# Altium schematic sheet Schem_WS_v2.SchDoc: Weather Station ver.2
size A3; DrawnBy: HienPhu; Engineer: HienPhu; Organization: QTech VietNam; Address1: ..........................; Address2: Đà Nẵng; Address3: Việt Nam; Address4: 09/2019; DocumentNumber: 1; Revision: 2.0; SheetNumber: 1; SheetTotal: 2
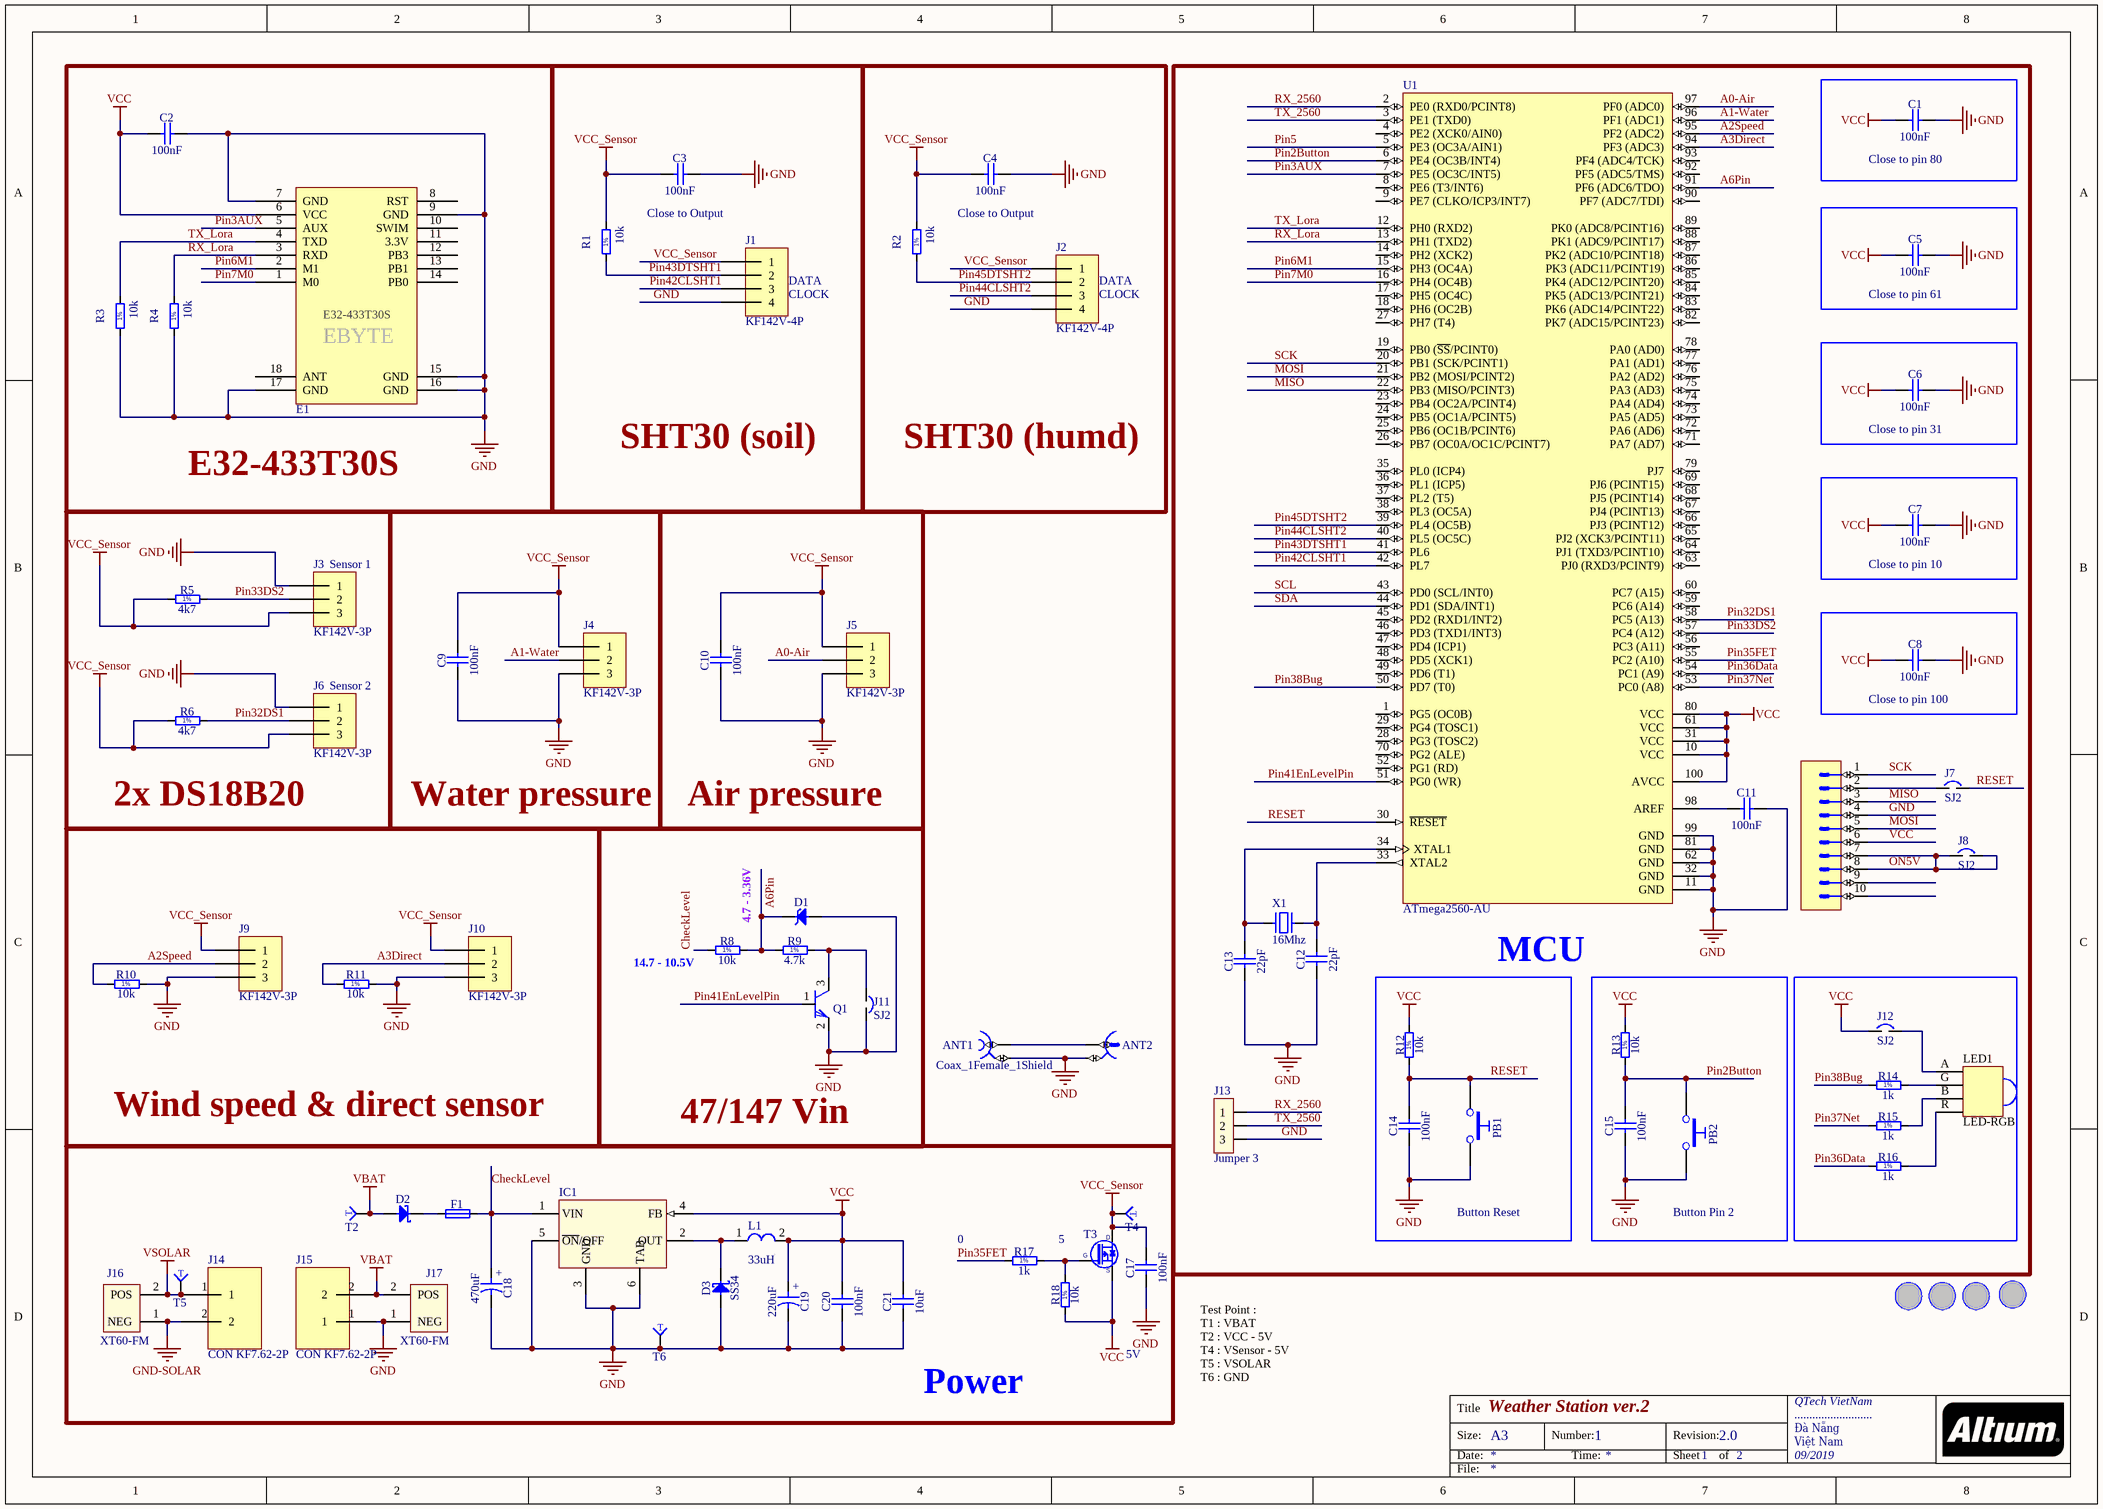
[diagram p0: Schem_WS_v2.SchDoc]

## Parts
ANT1  Coax_1Female_1Shield  [HUBER-SUHNER_85 SMA-50-0-101/111 NE]
ANT2  U.FL  [HIROSE_U.FL-R-SMT-1(10)]  (value not drawn)
C1  100nF  [CAPC1608X87N]
C2  100nF  [CAPC1608X87N]
C3  100nF  [CAPC1608X87N]
C4  100nF  [CAPC1608X87N]
C5  100nF  [CAPC1608X87N]
C6  100nF  [CAPC1608X87N]
C7  100nF  [CAPC1608X87N]
C8  100nF  [CAPC1608X87N]
C9  100nF  [CAPC1608X87N]
C10  100nF  [CAPC1608X87N]
C11  100nF  [CAPC1608X87N]
C12  22pF  [CAPC1608X87N]
C13  22pF  [CAPC1608X87N]
C14  100nF  [CAPC1608X87N]
C15  100nF  [CAPC1608X87N]
C17  100nF  [CAPC1608X87N]
C18  470uF  [CAPAE1030X1020N]
C19  220uF  [CAPMP6032X280N]
C20  100nF  [CAPC1608X87N]
C21  10uF  [CAPC2012X135N]
D1  BZV55-B5V1  [DIOMELF3515N]  (value not drawn)
D2  SS16  [DIOM5127X229N]  (value not drawn)
D3  SS34  [DIOM5127X229N]
E1  E32-T30S  [E32-433T30S]  (value not drawn)
F1  140mA-60V  [FUSRC4632X90N]  (value not drawn)
HOLE1  HOLE  [HOLE M3]  (value not drawn)
HOLE2  HOLE  [HOLE M3]  (value not drawn)
HOLE3  HOLE  [HOLE M3]  (value not drawn)
HOLE4  HOLE  [HOLE M3]  (value not drawn)
IC1  LM2596  [TO263-5]  (value not drawn)
J1  KF142V-4P  [CON KF142V-4P-5.08]
J2  KF142V-4P  [CON KF142V-4P-5.08]
J3  KF142V-3P  [CON KF142V-3P-5.08]
J4  KF142V-3P  [CON KF142V-3P-5.08]
J5  KF142V-3P  [CON KF142V-3P-5.08]
J6  KF142V-3P  [CON KF142V-3P-5.08]
J7  SJ2  [SJ2]
J8  SJ2  [SJ2]
J9  KF142V-3P  [CON KF142V-3P-5.08]
J10  KF142V-3P  [CON KF142V-3P-5.08]
J11  SJ2  [SJ2]
J12  SJ2  [SJ2]
J13  Jumper 3  [JP3]
J14  CON KF7.62-2P  [CON KF7.62-2P]
J15  CON KF7.62-2P  [CON KF7.62-2P]
J16  XT60-FM  [XT60-FM]
J17  XT60-FM  [XT60-FM]
JTAG1  Header 10  [3M_N2510-6002RB]  (value not drawn)
L1  33uH  [L_SMD]
LED1  LED-RGB  [LED-5MMRGBCA]
PB1  Push Button  [PB_TYCO_FSMSM]  (value not drawn)
PB2  Push Button  [PB_TYCO_FSMSM]  (value not drawn)
Q1  C1815  [SOT23]  (value not drawn)
R1  10k  [RESC1608X55N]
R2  10k  [RESC1608X55N]
R3  10k  [RESC1608X55N]
R4  10k  [RESC1608X55N]
R5  4k7  [RESC1608X55N]
R6  4k7  [RESC1608X55N]
R8  10k  [RESC1608X55N]
R9  4.7k  [RESC1608X55N]
R10  10k  [RESC1608X55N]
R11  10k  [RESC1608X55N]
R12  10k  [RESC1608X55N]
R13  10k  [RESC1608X55N]
R14  1k  [RESC1608X55N]
R15  1k  [RESC1608X55N]
R16  1k  [RESC1608X55N]
R17  1k  [RESC1608X55N]
R18  10k  [RESC1608X55N]
T2  Test Point  [TP1x1r]  (value not drawn)
T3  BSH203  [SOT95P230X110-3N]  (value not drawn)
T4  Test Point  [TP1x1r]  (value not drawn)
T5  Test Point  [TP1x1r]  (value not drawn)
T6  Test Point  [TP1x1r]  (value not drawn)
U1  ATmega2560-AU  [TQFP100L]
X1  16Mhz  [XT2]

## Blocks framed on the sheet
E32-433T30S: C2 E1 R3 R4
SHT30 (soil): C3 J1 R1
SHT30 (humd): C4 J2 R2
Button Reset: C11-C13 J7 J8 J12 J13 JTAG1 LED1 R14-R16 U1 X1
Close to pin 80: C1
Close to pin 61: C5
Close to pin 31: C6
Close to pin 10: C7
2x DS18B20: J3 J6 R5 R6
Water pressure: C9 J4
Air pressure: C10 J5
Close to pin 100: C8
Wind speed & direct sensor: J9 J10 R10 R11
47/147 Vin: D1 J11 Q1 R8 R9
MCU: C14 PB1 R12
Button Pin 2: C15 PB2 R13
Power: C17-C21 D2 D3 F1 IC1 J14-J17 L1 R17 R18 T2-T6

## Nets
GND: ANT1.2 ANT2.2 C1.2 C2.2 C3.2 C4.2 C5.2 C6.2 C7.2 C8.2 C9.1 C10.1 C11.2 C12.1 C13.1 C14.1 C15.1 C17.1 C18.2 C19.2 C20.1 C21.1 D1.2(A) D3.2(A) E1.7(GND) E1.9(GND) E1.15(GND) E1.16(GND) E1.17(GND) IC1.3(GND) IC1.5(~{ON}/OFF) IC1.6(TAB) J1.4 J2.4 J3.1 J4.3 J5.3 J6.1 J9.3 J10.3 J11.2 J13.3 J15.1 J17.1(NEG) JTAG1.4 PB1.2 PB2.2 Q1.2(E) R3.1 R4.1 R10.2 R11.2 T6.1 U1.11(GND) U1.32(GND) U1.62(GND) U1.81(GND) U1.99(GND)
GND-SOLAR: J14.2 J16.1(NEG)
VBAT: D2.2(A) J15.2 J17.2(POS) T2.1
VCC: C1.1 C2.1 C5.1 C6.1 C7.1 C8.1 C19.1 C20.2 C21.2 E1.6(VCC) IC1.4(FB) J12.1 JTAG1.6 L1.2 R12.2 R13.2 R18.1 T3.2(S) U1.10(VCC) U1.31(VCC) U1.61(VCC) U1.80(VCC) U1.100(AVCC)
VCC_Sensor: C3.1 C4.1 C9.2 C10.2 C17.2 J1.1 J2.1 J3.3 J4.1 J5.1 J6.3 J9.1 J10.1 R1.2 R2.2 R5.1 R6.1 T3.3(D) T4.1
VSOLAR: J14.1 J16.2(POS) T5.1
A0-Air: J5.2 U1.97(PF0_(ADC0))
A1-Water: J4.2 U1.96(PF1_(ADC1))
A2Speed: J9.2 R10.1 U1.95(PF2_(ADC2))
A3Direct: J10.2 R11.1 U1.94(PF3_(ADC3))
A6Pin: D1.1(C) R8.2 R9.1 U1.91(PF6_(ADC6/TDO))
CheckLevel: C18.1 F1.2 IC1.1(VIN) R8.1
MISO: JTAG1.3 U1.22(PB3_(MISO/PCINT3))
MOSI: JTAG1.5 U1.21(PB2_(MOSI/PCINT2))
ON5V: J8.1 J8.2 JTAG1.7 JTAG1.8
Pin2Button: C15.2 PB2.1 R13.1 U1.6(PE4_(OC3B/INT4))
Pin3AUX: E1.5(AUX) U1.7(PE5_(OC3C/INT5))
Pin5: U1.5(PE3_(OC3A/AIN1))
Pin6M1: E1.2(M1) U1.15(PH3_(OC4A))
Pin7M0: E1.1(M0) U1.16(PH4_(OC4B))
Pin32DS1: J6.2 R6.2 U1.58(PC5_(A13))
Pin33DS2: J3.2 R5.2 U1.57(PC4_(A12))
Pin35FET: R17.1 U1.55(PC2_(A10))
Pin36Data: R16.1 U1.54(PC1_(A9))
Pin37Net: R15.1 U1.53(PC0_(A8))
Pin38Bug: R14.1 U1.50(PD7_(T0))
Pin41EnLevelPin: Q1.1(B) U1.51(PG0_(WR))
Pin42CLSHT1: J1.3 U1.42(PL7)
Pin43DTSHT1: J1.2 R1.1 U1.41(PL6)
Pin44CLSHT2: J2.3 U1.40(PL5_(OC5C))
Pin45DTSHT2: J2.2 R2.1 U1.39(PL4_(OC5B))
RESET: C14.2 J7.2 PB1.1 R12.1 U1.30(~{RESET})
RX_2560: J13.1 U1.2(PE0_(RXD0/PCINT8))
RX_Lora: E1.3(RXD) R4.2 U1.13(PH1_(TXD2))
SCK: JTAG1.1 U1.20(PB1_(SCK/PCINT1))
SCL: U1.43(PD0_(SCL/INT0))
SDA: U1.44(PD1_(SDA/INT1))
TX_2560: J13.2 U1.3(PE1_(TXD0))
TX_Lora: E1.4(TXD) R3.2 U1.12(PH0_(RXD2))
NetANT1_1: ANT1.1 ANT2.1
NetC11_1: C11.1 U1.98(AREF)
NetC12_2: C12.2 U1.33(XTAL2) X1.1
NetC13_2: C13.2 U1.34(XTAL1) X1.2
NetD2_1: D2.1(C) F1.1
NetD3_1: D3.1(C) IC1.2(OUT) L1.1
NetJ7_1: J7.1 JTAG1.2
NetJ11_1: J11.1 Q1.3(C) R9.2
NetJ12_2: J12.2 LED1.A
NetLED1_B: LED1.B R15.2
NetLED1_G: LED1.G R14.2
NetLED1_R: LED1.R R16.2
NetR17_2: R17.2 R18.2 T3.1(G)

Not connected (* = marked no-connect by the designer): E1 8(RST) 10(SWIM) 11(3.3V) 12(PB3) 13(PB1) 14(PB0) 18(ANT); JTAG1 9 10; U1 1(PG5_(OC0B)) 4(PE2_(XCK0/AIN0)) 8(PE6_(T3/INT6)) 9(PE7_(CLKO/ICP3/INT7)) 14(PH2_(XCK2)) 17(PH5_(OC4C)) 18(PH6_(OC2B)) 19(PB0_(~{SS}/PCINT0)) 23(PB4_(OC2A/PCINT4)) 24(PB5_(OC1A/PCINT5)) 25(PB6_(OC1B/PCINT6)) 26(PB7_(OC0A/OC1C/PCINT7)) 27(PH7_(T4)) 28(PG3_(TOSC2)) 29(PG4_(TOSC1)) 35(PL0_(ICP4)) 36(PL1_(ICP5)) 37(PL2_(T5)) 38(PL3_(OC5A)) 45(PD2_(RXD1/INT2)) 46(PD3_(TXD1/INT3)) 47(PD4_(ICP1)) 48(PD5_(XCK1)) 49(PD6_(T1)) 52(PG1_(RD)) 56(PC3_(A11)) 59(PC6_(A14)) 60(PC7_(A15)) 63(PJ0_(RXD3/PCINT9)) 64(PJ1_(TXD3/PCINT10)) 65(PJ2_(XCK3/PCINT11)) 66(PJ3_(PCINT12)) 67(PJ4_(PCINT13)) 68(PJ5_(PCINT14)) 69(PJ6_(PCINT15)) 70(PG2_(ALE)) 71(PA7_(AD7)) 72(PA6_(AD6)) 73(PA5_(AD5)) 74(PA4_(AD4)) 75(PA3_(AD3)) 76(PA2_(AD2)) 77(PA1_(AD1)) 78(PA0_(AD0)) 79(PJ7) 82(PK7_(ADC15/PCINT23)) 83(PK6_(ADC14/PCINT22)) 84(PK5_(ADC13/PCINT21)) 85(PK4_(ADC12/PCINT20)) 86(PK3_(ADC11/PCINT19)) 87(PK2_(ADC10/PCINT18)) 88(PK1_(ADC9/PCINT17)) 89(PK0_(ADC8/PCINT16)) 90(PF7_(ADC7/TDI)) 92(PF5_(ADC5/TMS)) 93(PF4_(ADC4/TCK))

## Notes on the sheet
- Close to Output
- (near J1) DATA
- (near J1) CLOCK
- (near J2) DATA
- (near J2) CLOCK
- (near J3) Sensor 1
- (near J6) Sensor 2
- 4.7 - 3.36V
- (near R8) 14.7 - 10.5V
- 0
- 5
- 5V
- Test Point :
  T1 : VBAT
  T2 : VCC - 5V
  T4 : VSensor - 5V
  T5 : VSOLAR
  T6 : GND

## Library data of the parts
ANT1 = HUBER-SUHNER_85_SMA-50-0-101/111_NE: Part Description: SMA 50 Ohms Right Angle PCB Jack; Manufacturer: HUBER+SUHNER; Table: Miscellaneous
ANT2 = HIROSE_U.FL-R-SMT-1(10): Part Description: Up to 6GHz Ultra Small Surface Mount Male Coaxial Connectors U.FL Series; Manufacturer: HIROSE (HRS); Table: Miscellaneous
C1-C11 C14 C15 C17 C20 = CC0603_100NF_50V_10%_X7R: Non-polarised capacitor; Part Description: SMD Multilayer Chip Ceramic Capacitor; Manufacturer: GENERIC; Manufacturer1 Part Number: 223858615649; Voltage: 50V; TC: X7R; Tolerance: ±10%; Table: Capacitors SMD
C12 C13 = CC0603_22PF_50V_5%_NP0: Non-polarised capacitor; Part Description: SMD Multilayer Chip Ceramic Capacitor; Manufacturer: GENERIC; Manufacturer1 Part Number: 223886715229; Voltage: 50V; TC: NP0; Tolerance: ±5%; Table: Capacitors SMD
C18 = CAE1030-1020_470UF_25V_20%: Polarised capacitor; Part Description: Aluminum Electrolytic SMT Capacitor; Manufacturer: GENERIC; Manufacturer1 Part Number: EEEFK1E471AP; Voltage: 25V; Tolerance: ±20%; Table: Capacitors SMD
C19 = CTE6032-28_100UF_6.3V_10%_LESR0075: Polarised capacitor; Part Description: Low ESR 0R075 Solid Tantalum Chip Capacitor; Manufacturer: GENERIC; Manufacturer1 Part Number: TPSC107K006R0075; Value: 100uF; Voltage: 6.3V; Tolerance: ±10%; Table: Capacitors SMD
C21 = CC0805_10UF_16V_10%_X5R: Non-polarised capacitor; Part Description: SMD Multilayer Chip Ceramic Capacitor; Manufacturer: GENERIC; Manufacturer1 Part Number: C0805C106K4PAC; Voltage: 16V; TC: X5R; Tolerance: ±10%; Table: Capacitors SMD
D1 = BZV55-B5V1: Zener Diode; Part Description: Voltage Regulator Diode; Manufacturer: NXP SEMICONDUCTORS; Voltage: 5V1; Power: 500mW; Table: Diodes
D2 = SS16: Schottky Diode; Part Description: Surface Mount Schottky Barrier Rectifier; Manufacturer: VISHAY GENERAL SEMICONDUCTOR; Voltage: 60V; Power: 1A; Table: Diodes
D3 = SS16: Schottky Diode; Part Number: SS16; Part Description: Surface Mount Schottky Barrier Rectifier; Manufacturer: VISHAY GENERAL SEMICONDUCTOR; Voltage: 60V; Power: 1A; Table: Diodes
E1 = E32-433T30S: Lora Ebyte E32-T30S Module
F1 = FUSR1812_TYCO-MINISMDC014F: Fuse; Part Description: PolySwitch® PTC Overcurrent Protection Device; Manufacturer: TYCO ELECTRONICS; Table: Fuses
HOLE1-HOLE4 = HOLE M3
IC1 = LM2596-5V
J1 J2 = CON KF142V-4P-5.08
J3-J6 J9 J10 = CON KF142V-3P-5.08
J7 J8 J11 J12 = SJ2: Solder Jump2
J13 = JP3: Value: J3
J16 J17 = XT60-FM: MF: AMASS; MP: XT60-M
JTAG1 = 3M_N2510-6002RB: Connector 10 Male; Part Description: 10 Contacts - Straight .100'' x .100'' Low Profile Four-Wall Header, 2500 Serie; Manufacturer: 3M
L1 = L_SMD 33uH
PB1 PB2 = PB SPST 1NO-2NO: Push-Button Switch SPDT; Part Description: 12VDC 50mA SPST Tactile  Push-Button Switch; Manufacturer: TYCO ELECTRONICS; Manufacturer Part Number: FSMSM or 1437566-3; Table: Switches
Q1 = C1815: Q2SC1815; PSpiceTemplate: Q^@REFDES %c %b %e @MODEL; Vendor: Digikey
R1-R4 R12 R13 R18 = R0603_10K_1%_0.1W_100PPM: Resistor - 1%; Part Description: General Purpose Thick Film Chip Resistor; Manufacturer: GENERIC; Manufacturer1 Part Number: NRC06F1002TRF; Power: 0.1W; TC: ±100ppm/°C; Table: Resistors SMD
R5 R6 = R0603_4K7_1%_0.1W_100PPM: Resistor - 1%; Part Description: General Purpose Thick Film Chip Resistor; Manufacturer: GENERIC; Manufacturer1 Part Number: NRC06F4701TRF; Power: 0.1W; TC: ±100ppm/°C; Table: Resistors SMD
R8 = R0603_2M_1%_0.1W_100PPM: Resistor - 1%; Part Description: General Purpose Thick Film Chip Resistor; Manufacturer: GENERIC; Manufacturer1 Part Number: NRC06F2004TRF; Value: 2M; Power: 0.1W; TC: ±100ppm/°C; Table: Resistors SMD
R9 = R0603_1M_1%_0.1W_100PPM: Resistor - 1%; Part Description: General Purpose Thick Film Chip Resistor; Manufacturer: GENERIC; Manufacturer1 Part Number: NRC06F1004TRF; Value: 1M; Power: 0.1W; TC: ±100ppm/°C; Table: Resistors SMD
R10 R11 = R0603_160R_1%_0.1W_100PPM: Resistor - 1%; Part Description: General Purpose Thick Film Chip Resistor; Manufacturer: GENERIC; Manufacturer1 Part Number: NRC06F1600TRF; Value: 160; Power: 0.1W; TC: ±100ppm/°C; Table: Resistors SMD
R14-R17 = R0603_1K_1%_0.1W_100PPM: Resistor - 1%; Part Description: General Purpose Thick Film Chip Resistor; Manufacturer: GENERIC; Manufacturer1 Part Number: NRC06F1001TRF; Power: 0.1W; TC: ±100ppm/°C; Table: Resistors SMD
T2 T4-T6 = TP R1x1: Test Point Round 1x1 mm
T3 = BSH203: P-CHANNEL MOSFET WITH DIODE; Part Description: -30V -470mA P-Channel Enhancement Mode MOS Transistor; Manufacturer: NXP SEMICONDUCTORS; Table: Transistors
U1 = ATmega2560-AU: 8-bit AVR Microcontroller, 4.5-5.5V, 256KB Flash, 4KB EEPROM, 8KB SRAM, 86 GPIO pins, 100-pin TQFP, Industrial Grade (-40°C to 85°C), Pb-Free
X1 = XT2: Crystal, 32.768 KHz, -40 to 85 degC, 3.2 x 1.5 x 0.9 mm SMD; Value: 4Mhz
